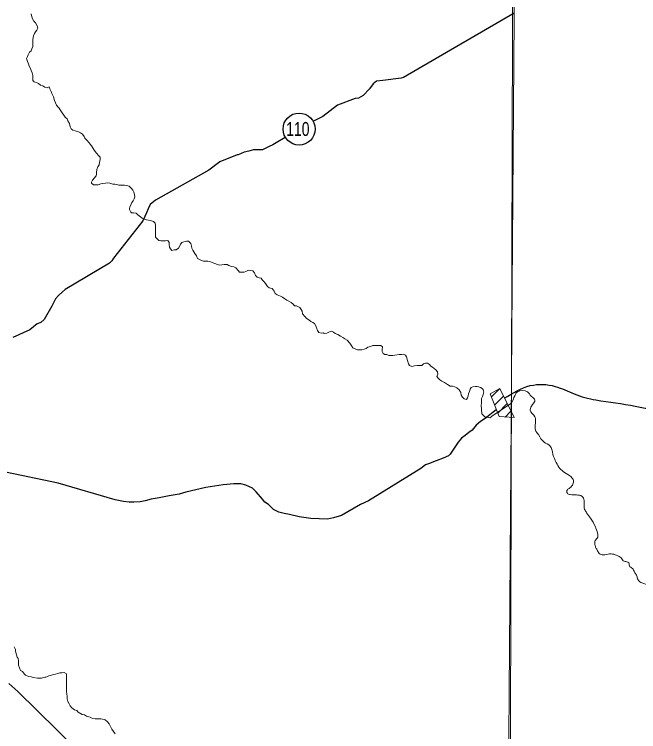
# Model space of a CAD drawing. Extents: x -1643653 to 4543381, y 1624270 to 13878484.
# Drawn here: x 616027 to 619158, y 8902830 to 8906430 of the extents above; entities that cross this region are included whole.
import ezdxf
from ezdxf.enums import TextEntityAlignment as Align

# ---------------------------------------------------------------- set-up
doc = ezdxf.new("R2010")
doc.units = 0
doc.header["$LTSCALE"] = 160
doc.layers.add('6', color=7, linetype='Continuous', lineweight=13)
doc.layers.add('60', color=7, linetype='Continuous', lineweight=13)

msp = doc.modelspace()

# ---------------------------------------------------------------- linework, layer by layer
at = {"layer": '6'}
for p, q in [((618419.3, 8904510), (618459.5, 8904550.2)), ((618435.1, 8904469.2), (618480.5, 8904514.6)), ((618451, 8904428.5), (618499.1, 8904476.6)), ((618488.1, 8904409.1), (618517.7, 8904438.6))]:
    msp.add_line(p, q, dxfattribs=at)
for points in [[(618663, 8924716.1), (618558.3, 8909803.7), (618456.5, 8896026.7)], [(616110.9, 8906433.2), (616113.9, 8906417.9), (616117.9, 8906407.7), (616124.9, 8906396.4), (616133, 8906387.2), (616142.1, 8906372.9), (616144, 8906360.7), (616139.9, 8906350.5), (616133.7, 8906342.4), (616127.6, 8906334.3), (616123.4, 8906322.1), (616120.2, 8906304.8), (616120.1, 8906290.5), (616120.1, 8906279.3), (616120, 8906269.1), (616114.8, 8906256.9), (616110.7, 8906246.8), (616102.5, 8906239.7), (616096.3, 8906227.5), (616092.2, 8906218.4), (616088, 8906208.2), (616092, 8906192.9), (616098, 8906181.7), (616101, 8906170.4)], [(616101, 8906170.4), (616108, 8906159.2), (616112, 8906149), (616116, 8906136.7), (616119, 8906123.4), (616119.9, 8906110.2), (616119.8, 8906099), (616125.9, 8906090.8), (616138.1, 8906087.7), (616147.2, 8906083.5), (616158.3, 8906075.3), (616170.5, 8906072.2), (616179.6, 8906064), (616191.8, 8906061.9), (616201, 8906065.9), (616204, 8906055.7), (616211, 8906042.4), (616215, 8906033.2), (616223, 8906015.8), (616229, 8905998.5), (616233, 8905986.2), (616239, 8905975), (616245.1, 8905966.8), (616252.1, 8905959.6), (616257.2, 8905950.4), (616267.2, 8905936.1), (616274.3, 8905923.8), (616282.3, 8905914.6), (616291.4, 8905906.4), (616295.4, 8905896.2), (616303.5, 8905881.8), (616307.4, 8905865.5), (616312.5, 8905856.3), (616320.5, 8905849.1), (616332.7, 8905845), (616349, 8905840.8), (616359.1, 8905835.6)], [(616359.1, 8905835.6), (616369.2, 8905828.4), (616376.3, 8905817.2), (616380.3, 8905808), (616391.4, 8905797.7), (616400.5, 8905786.5), (616408.5, 8905777.2), (616416.6, 8905765), (616426.7, 8905748.6), (616438.8, 8905733.2), (616450.9, 8905720.9), (616458, 8905713.8), (616457.9, 8905701.6), (616453.7, 8905687.3), (616451.6, 8905675.1), (616445.4, 8905664.9), (616441.2, 8905651.7), (616438.2, 8905636.4), (616439.5, 8905627.9), (616437, 8905619.4), (616419.4, 8905598.1), (616413.4, 8905587.8), (616413.3, 8905582.6), (616424.5, 8905575.4), (616435.6, 8905574.3), (616447.8, 8905574.3), (616461.1, 8905580.3), (616469.2, 8905581.7), (616483.5, 8905583.2), (616495.7, 8905584.1), (616505.6, 8905583.6), (616520.7, 8905578.7), (616530.4, 8905578.1), (616540.1, 8905575.7), (616551, 8905573.2), (616566.8, 8905573.2), (616579.5, 8905573.2), (616589.8, 8905572), (616602.6, 8905568.4), (616607.5, 8905563.1), (616614.5, 8905555.9), (616620.6, 8905547.7), (616626.6, 8905538.5), (616629.6, 8905526.2), (616630.5, 8905514), (616627.4, 8905503.8), (616623.2, 8905493.7), (616616.5, 8905485.2), (616611.7, 8905474.3), (616606.2, 8905463.3), (616604.4, 8905455.4), (616605, 8905450), (616611.1, 8905437.2), (616614.7, 8905433.6), (616624.9, 8905433.6), (616637.1, 8905432.5), (616646.2, 8905423.2), (616659.3, 8905414), (616668.4, 8905406.8), (616679.6, 8905402.6), (616689.8, 8905398.5), (616699.9, 8905397.4), (616710.1, 8905395.3), (616724.3, 8905390.1), (616732.4, 8905382.9)], [(616732.4, 8905382.9), (616735.3, 8905369.7), (616735.3, 8905359.5), (616735.2, 8905344.2), (616735, 8905325.9), (616734.9, 8905312.6), (616742, 8905304.4), (616752.1, 8905295.2), (616762.3, 8905294.1), (616773.5, 8905294.1), (616784.7, 8905294), (616796.9, 8905294.9), (616802.9, 8905285.7), (616802.8, 8905275.5), (616804.8, 8905262.3), (616810.8, 8905254.1), (616816.9, 8905244.9), (616828.1, 8905247.9), (616838.2, 8905247.8), (616850.5, 8905255.9), (616856.7, 8905268.1), (616860.8, 8905277.2), (616867, 8905285.3), (616877.2, 8905288.3), (616890.4, 8905291.3), (616900.6, 8905291.2), (616912.7, 8905279.9), (616915.7, 8905266.7), (616916.6, 8905256.5), (616921.7, 8905246.2), (616931.7, 8905229.9), (616939.8, 8905218.6), (616945.8, 8905205.3), (616954.9, 8905199.2), (616965, 8905194), (616976.2, 8905190.9), (616986.4, 8905190.8)], [(616986.4, 8905190.8), (616996.5, 8905190.7), (617006.7, 8905189.7), (617018.9, 8905185.5), (617032.1, 8905179.3), (617046.3, 8905175.1), (617056.4, 8905172), (617067.6, 8905173), (617078.8, 8905174.9), (617094.1, 8905174.8), (617103.2, 8905169.7), (617116.4, 8905165.5), (617127.6, 8905163.4), (617137.7, 8905158.2), (617148.8, 8905144.9), (617156.9, 8905136.7), (617167.1, 8905135.7), (617179.3, 8905135.6), (617188.5, 8905139.6), (617200.7, 8905146.6), (617212.9, 8905144.5), (617223.1, 8905143.4), (617231.1, 8905132.2), (617237.1, 8905118.9), (617245.2, 8905110.7), (617255.4, 8905107.6), (617265.5, 8905106.5), (617269.5, 8905097.3), (617281.7, 8905086), (617289.7, 8905073.7), (617295.8, 8905064.5), (617304.9, 8905058.4), (617319.1, 8905054.2), (617329.2, 8905040.9), (617334.2, 8905029.7), (617345.3, 8905022.4), (617361.6, 8905016.2), (617371.7, 8905010.1), (617383.8, 8905001.8), (617392.9, 8904995.7), (617404.1, 8904990.5), (617415.2, 8904984.3), (617425.3, 8904975.1), (617432.4, 8904966.9), (617442.6, 8904966.8), (617458.8, 8904958.6), (617464.8, 8904949.3), (617469.9, 8904940.1), (617472.8, 8904927.9), (617483.6, 8904913.2), (617490, 8904906.8), (617490, 8904904.7), (617503.1, 8904897.1), (617513.3, 8904888.9), (617523.5, 8904884.2), (617532.9, 8904877.9), (617539.1, 8904867), (617542.2, 8904856.1), (617546.9, 8904843.6), (617554.7, 8904834.2), (617568.8, 8904829.5), (617576.6, 8904831.1), (617581.2, 8904827.9), (617594.2, 8904829.3), (617607.5, 8904836.4)], [(617607.5, 8904836.4), (617617.7, 8904839.4), (617627.8, 8904835.2), (617635.9, 8904829.1), (617649.1, 8904822.9), (617662.3, 8904815.6), (617674.4, 8904808.4), (617684.6, 8904802.2), (617695.7, 8904795.1), (617709.9, 8904780.7), (617716.9, 8904769.4), (617725, 8904757.2), (617736.1, 8904751), (617748.3, 8904746.8), (617758.4, 8904745.8), (617769.6, 8904746.7), (617781.9, 8904749.7), (617791.1, 8904753.7), (617800.2, 8904759.7), (617812.5, 8904763.7), (617824.7, 8904767.7), (617835.9, 8904768.7), (617855.2, 8904768.6), (617865.4, 8904768.5), (617872.5, 8904761.3), (617872.4, 8904748.1), (617872.3, 8904737.9), (617876.3, 8904727.7), (617885.5, 8904723.5), (617895.6, 8904722.4), (617904.7, 8904718.3), (617914.9, 8904718.2), (617925.1, 8904718.2), (617935.3, 8904719.1), (617957.7, 8904723.1), (617967.8, 8904723), (617979, 8904724)], [(617979, 8904724), (617989.2, 8904719.8), (617993.2, 8904710.6), (617998.2, 8904693.3), (618004.1, 8904676.9), (618008.2, 8904667.7), (618020.3, 8904663.6), (618034.6, 8904665.5), (618046.8, 8904667.5), (618057, 8904667.4), (618071.2, 8904668.3), (618078.4, 8904675.4), (618089.6, 8904679.4), (618099.8, 8904679.4), (618108.9, 8904672.2), (618114.9, 8904664), (618124.1, 8904658.8), (618132.2, 8904652.7), (618140.2, 8904646.5), (618148.3, 8904635.3), (618151.3, 8904625.1), (618146.1, 8904612.9), (618153.2, 8904603.6), (618160.2, 8904596.5), (618171.4, 8904589.3), (618184.6, 8904582.1), (618199.8, 8904572.8), (618212.9, 8904564.6), (618225.1, 8904563.4), (618235.3, 8904560.3), (618245.4, 8904556.2), (618257.6, 8904545.9), (618265.6, 8904531.6), (618267.5, 8904519.4), (618274.6, 8904508.1), (618283.7, 8904500.9), (618293.8, 8904496.8), (618300, 8904505.9), (618303.1, 8904516.1), (618304.2, 8904526.3), (618309, 8904537.8), (618312.5, 8904548.5), (618317.6, 8904556.7), (618326.8, 8904561.1), (618339.4, 8904562.8), (618348.3, 8904562.8), (618355.5, 8904561.1), (618364.4, 8904557.5), (618373.3, 8904552.1), (618378.7, 8904546.7), (618380.5, 8904539.6), (618381.6, 8904536), (618378.4, 8904521.7), (618374.3, 8904511.6), (618370.2, 8904501.4), (618370.1, 8904491.2), (618369, 8904479), (618367.9, 8904468.8), (618370.7, 8904425), (618386.8, 8904409.6), (618410.9, 8904405.3), (618427, 8904416), (618519.7, 8904479.2)], [(616025.4, 8903256.1), (616032.4, 8903242.8), (616031.9, 8903233.8), (616036.9, 8903215.3), (616040.3, 8903203.6), (616045.3, 8903196.9), (616047.3, 8903187.7), (616047.2, 8903175.5), (616048.1, 8903164.3), (616053.1, 8903151), (616058.1, 8903136.7), (616067.2, 8903131.6), (616077.1, 8903118.2), (616082.1, 8903113.2), (616097.1, 8903106.5)], [(616097.1, 8903106.5), (616110.5, 8903104.8), (616120.6, 8903101.5), (616142.3, 8903098.2), (616162.4, 8903098.2), (616179.1, 8903103.2), (616184.1, 8903103.2), (616189.1, 8903104.8), (616199.2, 8903109.9), (616207.5, 8903111.5), (616223.8, 8903117.3), (616234, 8903119.3), (616245.2, 8903121.3), (616254.4, 8903125.3), (616265.6, 8903125.2), (616276.8, 8903126.2), (616287.9, 8903121), (616288.8, 8903109.8), (616288.8, 8903098.6), (616288.7, 8903087.4), (616288.6, 8903076.2), (616288.5, 8903059.9), (616288.4, 8903040.5), (616288.3, 8903030.3), (616289.3, 8903020.1), (616291.2, 8903005.8), (616292.1, 8902994.6), (616295.1, 8902981.4), (616301.1, 8902969.1), (616307.2, 8902959.9), (616315.2, 8902949.7), (616327.9, 8902939.1), (616339.5, 8902936.3), (616346.3, 8902927.4), (616366.4, 8902915.6), (616378.1, 8902914), (616388.1, 8902907.3)], [(616388.1, 8902907.3), (616406.5, 8902902.2), (616418.2, 8902895.6), (616431.6, 8902893.9), (616441.7, 8902893.9), (616460.1, 8902893.9), (616476.8, 8902890.5), (616482.6, 8902888.5), (616493.8, 8902879.2), (616501.8, 8902870), (616510.9, 8902852.7), (616515.9, 8902842.4), (616524, 8902830.2), (616532, 8902818.9)]]:
    msp.add_lwpolyline(points, dxfattribs=at)
for points in [[(618535.2, 8909853.3), (607574.3, 8909890.7), (607543.3, 8898835.3), (618504.2, 8898795.8)], [(618462.3, 8904551.7), (618413.4, 8904525.1), (618457.8, 8904411), (618533.6, 8904406.1)]]:
    msp.add_lwpolyline(points, close=True, dxfattribs=at)
at = {"layer": '6', "lineweight": 25}
for points in [[(618533.2, 8906436.6), (617978.2, 8906112.6), (617967, 8906109.6), (617874.3, 8906097.6), (617843.7, 8906095.6), (617826.3, 8906081.3), (617808.9, 8906055.9), (617776.2, 8906022.3), (617753.7, 8906010.2), (617735.4, 8906008.2), (617647.6, 8905973.7), (617574.1, 8905917.8), (617526.6, 8905893.4)], [(617384.3, 8905811.9), (617340.2, 8905785.8), (617322.9, 8905774.6), (617304.5, 8905767.5), (617270.8, 8905750.2), (617226, 8905750.3), (617202.5, 8905743.2), (617180.1, 8905738.2), (617149.5, 8905726), (617144.4, 8905726), (617057.7, 8905690.5), (617001.5, 8905648.8), (616735, 8905497.5), (616708.4, 8905475.2), (616698.2, 8905454.8), (616689.9, 8905434.4), (616681.7, 8905415.1), (616671.4, 8905393.7), (616524, 8905206.5), (616515.8, 8905193.3), (616504.6, 8905181.1), (616281, 8905049.1), (616266.7, 8905035.8), (616248.2, 8905018.6), (616233.9, 8905002.3), (616214.4, 8904965.6), (616176.5, 8904899.5), (616160.1, 8904883.2), (616140.7, 8904876.1), (616105, 8904846.6), (616019.2, 8904809.1)], [(618442.8, 8904444.9), (618387.6, 8904401.3), (618365.2, 8904386.1), (618343.7, 8904367.8), (618323.2, 8904343.3), (618306.9, 8904331.1), (618288.5, 8904315.9), (618269.1, 8904302.7), (618252.7, 8904283.3), (618229.2, 8904247.7), (618212.8, 8904222.3), (618203.6, 8904215.2), (618177, 8904202), (618142.3, 8904189.8), (618104.6, 8904174.6), (618089.3, 8904169.5), (618064.8, 8904150.2), (617802.3, 8903987.7), (617762.5, 8903970.5), (617667.6, 8903914.6), (617626.8, 8903902.4), (617597.2, 8903896.4), (617513.6, 8903899.6), (617454.6, 8903907.9), (617406.7, 8903919.2), (617380.3, 8903925.3), (617352.8, 8903931.5), (617326.3, 8903944.8), (617302, 8903969.3), (617283.7, 8903982.5), (617271.5, 8903996.8), (617239, 8904033.6), (617221.8, 8904051.9), (617187.2, 8904067.3), (617162.8, 8904073.4), (617128.1, 8904074.5), (617074.1, 8904069.5), (616987.5, 8904055.4), (616887.5, 8904032.2), (616853.9, 8904022.1), (616803.9, 8904014), (616752.9, 8904003.9), (616713.2, 8903996.8), (616683.6, 8903987.7), (616658.1, 8903983.7), (616626.5, 8903981.7), (616602.1, 8903981.8), (616574.6, 8903984.9), (616532.8, 8903993.1), (616245.8, 8904077.2), (615725.6, 8904186.1)], [(615998.6, 8903072.1), (616044.3, 8903031.2), (616338.7, 8902741.3)]]:
    msp.add_lwpolyline(points, dxfattribs=at)
msp.add_circle((617454.9, 8905854.7), 80.3, dxfattribs=at)
msp.add_spline([(618487.4, 8904504.8), (618614.5, 8904566.7), (618739.5, 8904562.9), (618834.2, 8904525), (618944, 8904494.7), (619141, 8904464.4), (619269.8, 8904426.5), (619413.7, 8904347), (619610.7, 8904248.5), (619898.6, 8904070.5), (620175.1, 8903918.9), (620288.7, 8903884.9), (620489.5, 8903873.5), (620815.2, 8903858.3), (621019.8, 8903831.8), (621319, 8903718.2), (621610.7, 8903631.1), (621785, 8903608.3), (621841.8, 8903604.6), (621917.5, 8903551.5), (622012.2, 8903479.6), (622084.2, 8903426.5), (622194.1, 8903396.2), (622315.3, 8903388.6)], degree=3, dxfattribs=at)
at = {"layer": '6'}
msp.add_spline([(618519.7, 8904479.2), (618532.8, 8904506.8), (618550.3, 8904535.8), (618599.7, 8904535.8), (618620.1, 8904512.6), (618637.5, 8904495.1), (618620.1, 8904463.1), (618614.2, 8904442.8), (618637.5, 8904410.8), (618640.4, 8904378.8), (618640.4, 8904343.9), (618655, 8904320.7), (618684, 8904282.9), (618713.1, 8904265.4), (618727.6, 8904221.8), (618744.8, 8904180.8), (618762.3, 8904151.5), (618786.7, 8904131), (618818.9, 8904108.6), (618830.6, 8904091), (618828.7, 8904072.5), (618812.1, 8904053), (618800.4, 8904044.2), (618800.4, 8904026.6), (618815, 8904019.8), (618846.2, 8904017.8), (618874.5, 8904011), (618881.3, 8904002.2), (618885.2, 8903978.8), (618887.2, 8903945.6), (618897, 8903929), (618916.5, 8903901.7), (618940.9, 8903858.8), (618951.6, 8903826.6), (618952.6, 8903806.1), (618939.9, 8903788.6), (618938.9, 8903768.1), (618943.8, 8903752.4), (618951.6, 8903737.8), (618964.3, 8903721.2), (618988.7, 8903717.3), (619019.9, 8903722.2), (619047.2, 8903715.4), (619070.6, 8903701.7), (619085.3, 8903685.1), (619103.8, 8903681.2), (619110.6, 8903673.4), (619111.6, 8903661.7), (619127.2, 8903649.3), (619137, 8903630.8), (619146.7, 8903616.1), (619152.6, 8903596.6), (619164.3, 8903581.9), (619184.8, 8903573.2), (619214.1, 8903563.4)], degree=3, dxfattribs=at)
at = {"layer": '60', "lineweight": 25}
msp.add_spline([(814781, 9009175.5), (814787.2, 9009173.4), (814796.9, 9009173.4), (814799.4, 9009172.4), (814805.1, 9009174.5), (814805.6, 9009176.5), (814811.7, 9009179.5), (814811.7, 9009179.5), (814801.5, 9009181), (814790.7, 9009181.5), (814784.1, 9009183.1), (814777.4, 9009185.1), (814778.4, 9009175.5)], degree=3, dxfattribs=at)

# ---------------------------------------------------------------- texts
at = {"layer": '6', "width": 0.75}
msp.add_text('110', height=70, dxfattribs=at).set_placement((617448.6, 8905820), align=Align.CENTER)

doc.saveas('drawing.dxf')
